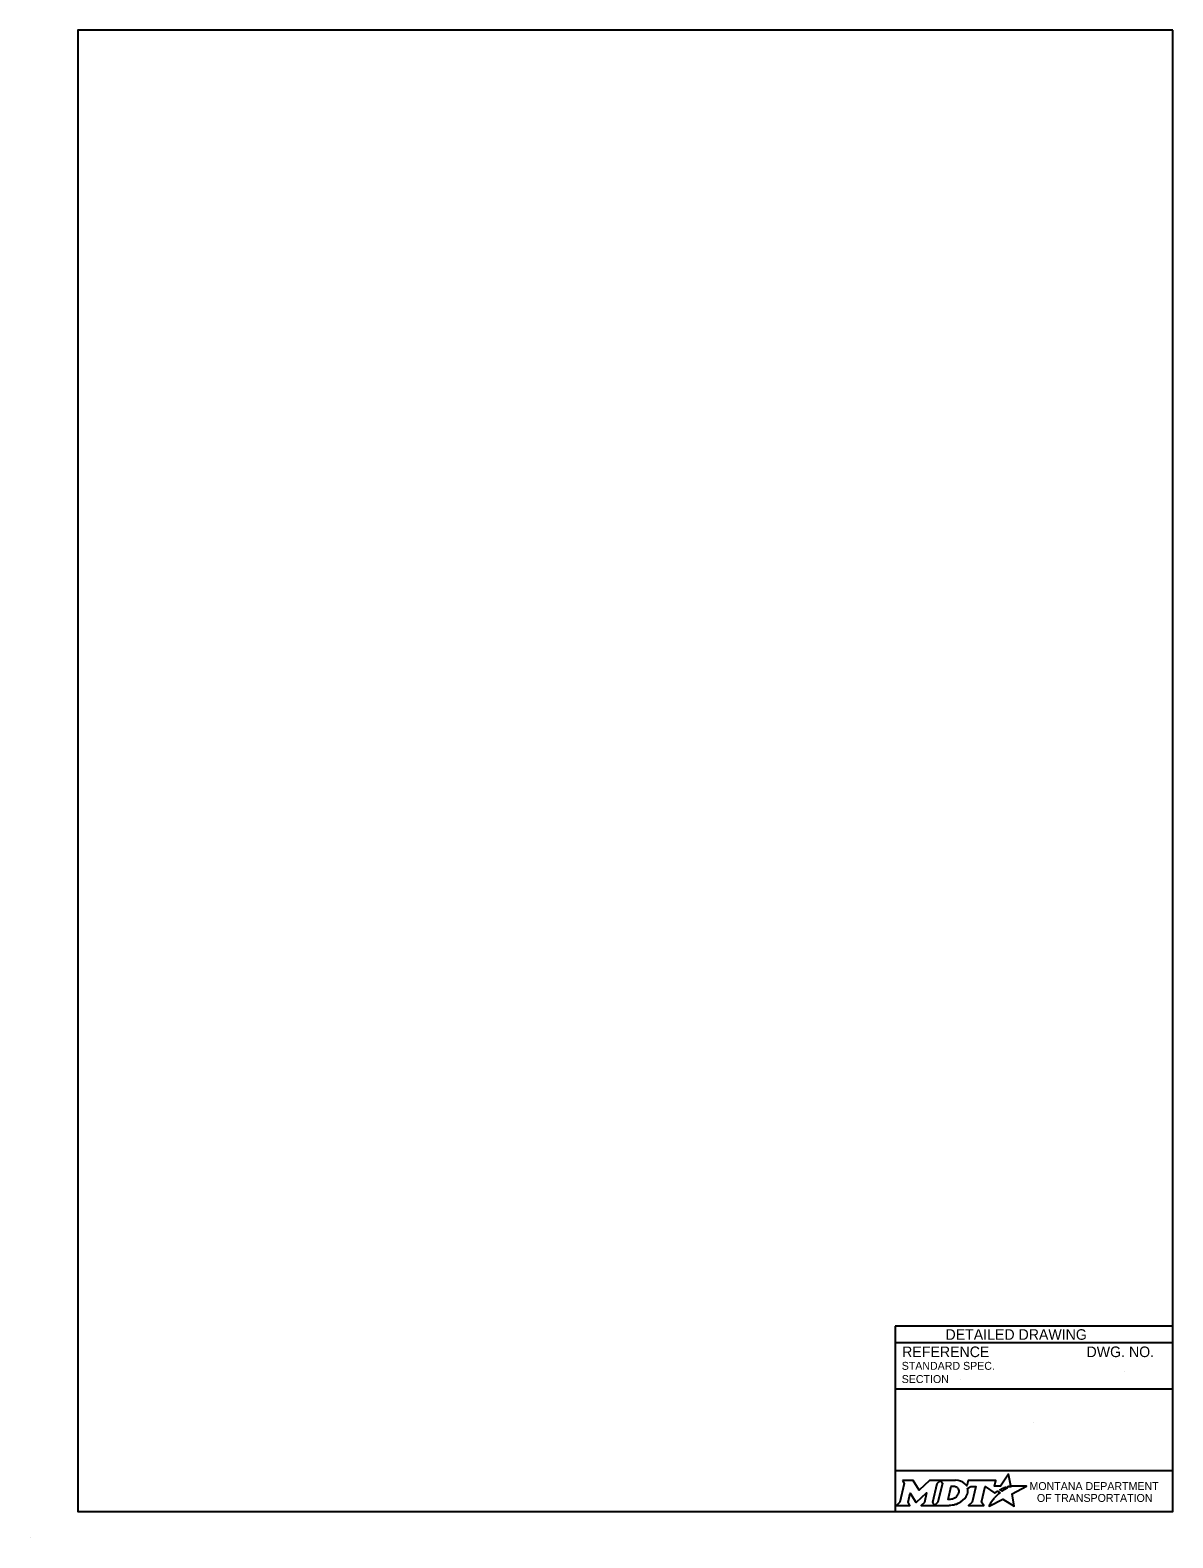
# Model space of a CAD drawing. Extents: x 49991.4 to 50021, y 49987.6 to 50011.4.
# Drawn here: x 49999.98 to 50008.61, y 49999.86 to 50011.26 of the extents above; entities that cross this region are included whole.
import ezdxf

# ---------------------------------------------------------------- set-up
doc = ezdxf.new("R2010")
doc.units = 0
doc.layers.add('Level 1', color=7, linetype='Continuous')
doc.layers.add('Level 2', color=7, linetype='Continuous')

msp = doc.modelspace()

# ---------------------------------------------------------------- linework, layer by layer
at = {"layer": 'Level 1'}
msp.add_line((49999.977, 49999.862), (49999.977, 49999.862), dxfattribs=at)
msp.add_lwpolyline([(50008.615, 50011.263), (50000.336, 50011.263), (50000.336, 50000.062), (50008.615, 50000.062)], close=True, dxfattribs=at)
at = {"layer": 'Level 2'}
for p, q in [((50008.615, 50001.462), (50006.515, 50001.462)), ((50006.515, 50001.462), (50006.515, 50000.062)), ((50008.615, 50001.337), (50006.515, 50001.337)), ((50007.009, 50001.063), (50007.009, 50001.063)), ((50008.251, 50001.122), (50008.251, 50001.122)), ((50008.615, 50000.987), (50006.515, 50000.987)), ((50007.565, 50000.738), (50007.565, 50000.738)), ((50008.615, 50000.369), (50006.515, 50000.369))]:
    msp.add_line(p, q, dxfattribs=at)
for points in [[(50007.377, 50000.245), (50007.367, 50000.25), (50007.378, 50000.253), (50007.39, 50000.255), (50007.373, 50000.345), (50007.313, 50000.254), (50007.266, 50000.253), (50007.276, 50000.297), (50007.067, 50000.297), (50007.057, 50000.255), (50007.051, 50000.263)], [(50006.57, 50000.297), (50006.584, 50000.274), (50006.551, 50000.131), (50006.525, 50000.108), (50006.627, 50000.108), (50006.613, 50000.131), (50006.629, 50000.201), (50006.673, 50000.132), (50006.678, 50000.132), (50006.753, 50000.202), (50006.737, 50000.13), (50006.712, 50000.108), (50006.814, 50000.108), (50006.8, 50000.132), (50006.833, 50000.274)], [(50006.833, 50000.274), (50006.859, 50000.297), (50006.776, 50000.297), (50006.697, 50000.224), (50006.652, 50000.297), (50006.57, 50000.297)], [(50006.972, 50000.297), (50006.859, 50000.297), (50006.873, 50000.275), (50006.839, 50000.131), (50006.814, 50000.108), (50006.925, 50000.108)], [(50006.996, 50000.211), (50006.995, 50000.203), (50006.992, 50000.193), (50006.988, 50000.185), (50006.982, 50000.178), (50006.976, 50000.171), (50006.968, 50000.164), (50006.959, 50000.16), (50006.95, 50000.156), (50006.941, 50000.154), (50006.932, 50000.153), (50006.916, 50000.153), (50006.94, 50000.253), (50006.956, 50000.253), (50006.963, 50000.252), (50006.971, 50000.25), (50006.977, 50000.247), (50006.983, 50000.243), (50006.988, 50000.238), (50006.992, 50000.232), (50006.995, 50000.226), (50006.996, 50000.218), (50006.996, 50000.215), (50006.996, 50000.211)], [(50007.064, 50000.238), (50007.088, 50000.251), (50007.125, 50000.251), (50007.097, 50000.131), (50007.069, 50000.108), (50007.185, 50000.108), (50007.168, 50000.131), (50007.196, 50000.251), (50007.268, 50000.2), (50007.289, 50000.215), (50007.309, 50000.204)], [(50007.253, 50000.148), (50007.237, 50000.124), (50007.233, 50000.116), (50007.227, 50000.107), (50007.225, 50000.103), (50007.33, 50000.156), (50007.414, 50000.101), (50007.401, 50000.194), (50007.508, 50000.252), (50007.458, 50000.253), (50007.428, 50000.253), (50007.407, 50000.254), (50007.401, 50000.252), (50007.396, 50000.251), (50007.387, 50000.249), (50007.377, 50000.245)], [(50007.327, 50000.217), (50007.324, 50000.215), (50007.306, 50000.225), (50007.316, 50000.231), (50007.32, 50000.233), (50007.329, 50000.237), (50007.335, 50000.239), (50007.343, 50000.243), (50007.35, 50000.245), (50007.362, 50000.238), (50007.358, 50000.236), (50007.353, 50000.233), (50007.349, 50000.231), (50007.344, 50000.228), (50007.342, 50000.227), (50007.339, 50000.225), (50007.337, 50000.224), (50007.334, 50000.222), (50007.332, 50000.221), (50007.329, 50000.219), (50007.327, 50000.217)], [(50006.97, 50000.116), (50006.979, 50000.118), (50006.992, 50000.124), (50007.012, 50000.135)], [(50007.267, 50000.164), (50007.267, 50000.164)]]:
    msp.add_lwpolyline(points, dxfattribs=at)
for centre, radius, start, end in [((50006.995, 50000.219), 0.0709, 339.5329, 15.8582), ((50006.951, 50000.236), 0.118, 300.9103, 339.1383)]:
    msp.add_arc(centre, radius, start, end, dxfattribs=at)
for centre, major_axis, ratio, start_param, end_param in [((50006.97, 50000.25), (0.0834, -0.0037), 0.568097, 0.61298, 1.570796), ((50007.026, 50000.257), (0.0361, -0.0295), 0.469099, 1.225588, 1.570796), ((50006.925, 50000.257), (0, 0.148), 0.987302, 3.139398, 3.456847), ((50007.26, 50000.156), (-0.00694, -0.00806), 0.008222, 0, 3.137361), ((50007.276, 50000.174), (-0.0098, -0.0102), 0.016458, 3.141593, 6.279097), ((50007.297, 50000.194), (-0.0112, -0.0097), 0.021651, 3.157348, 6.283185)]:
    msp.add_ellipse(centre, major_axis=major_axis, ratio=ratio, start_param=start_param, end_param=end_param, dxfattribs=at)

# ---------------------------------------------------------------- texts
for s, height, p in [('DETAILED DRAWING', 0.0799, (50006.896, 50001.36)), ('REFERENCE', 0.08, (50006.568, 50001.229)), ('DWG. NO.', 0.08, (50007.962, 50001.229)), ('STANDARD SPEC.', 0.06, (50006.565, 50001.133)), ('SECTION', 0.06, (50006.565, 50001.033)), ('MONTANA DEPARTMENT', 0.06, (50007.531, 50000.224)), ('OF TRANSPORTATION', 0.06, (50007.587, 50000.134))]:
    msp.add_text(s, height=height, dxfattribs=at).set_placement(p)

doc.saveas('drawing.dxf')
